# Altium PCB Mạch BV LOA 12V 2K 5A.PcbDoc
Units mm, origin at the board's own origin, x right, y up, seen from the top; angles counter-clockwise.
Board outline 69.27 x 57.96 mm, 2 copper layers (Top Layer, Bottom Layer); 0 components, 34 nets, 68 pads, 0 vias.
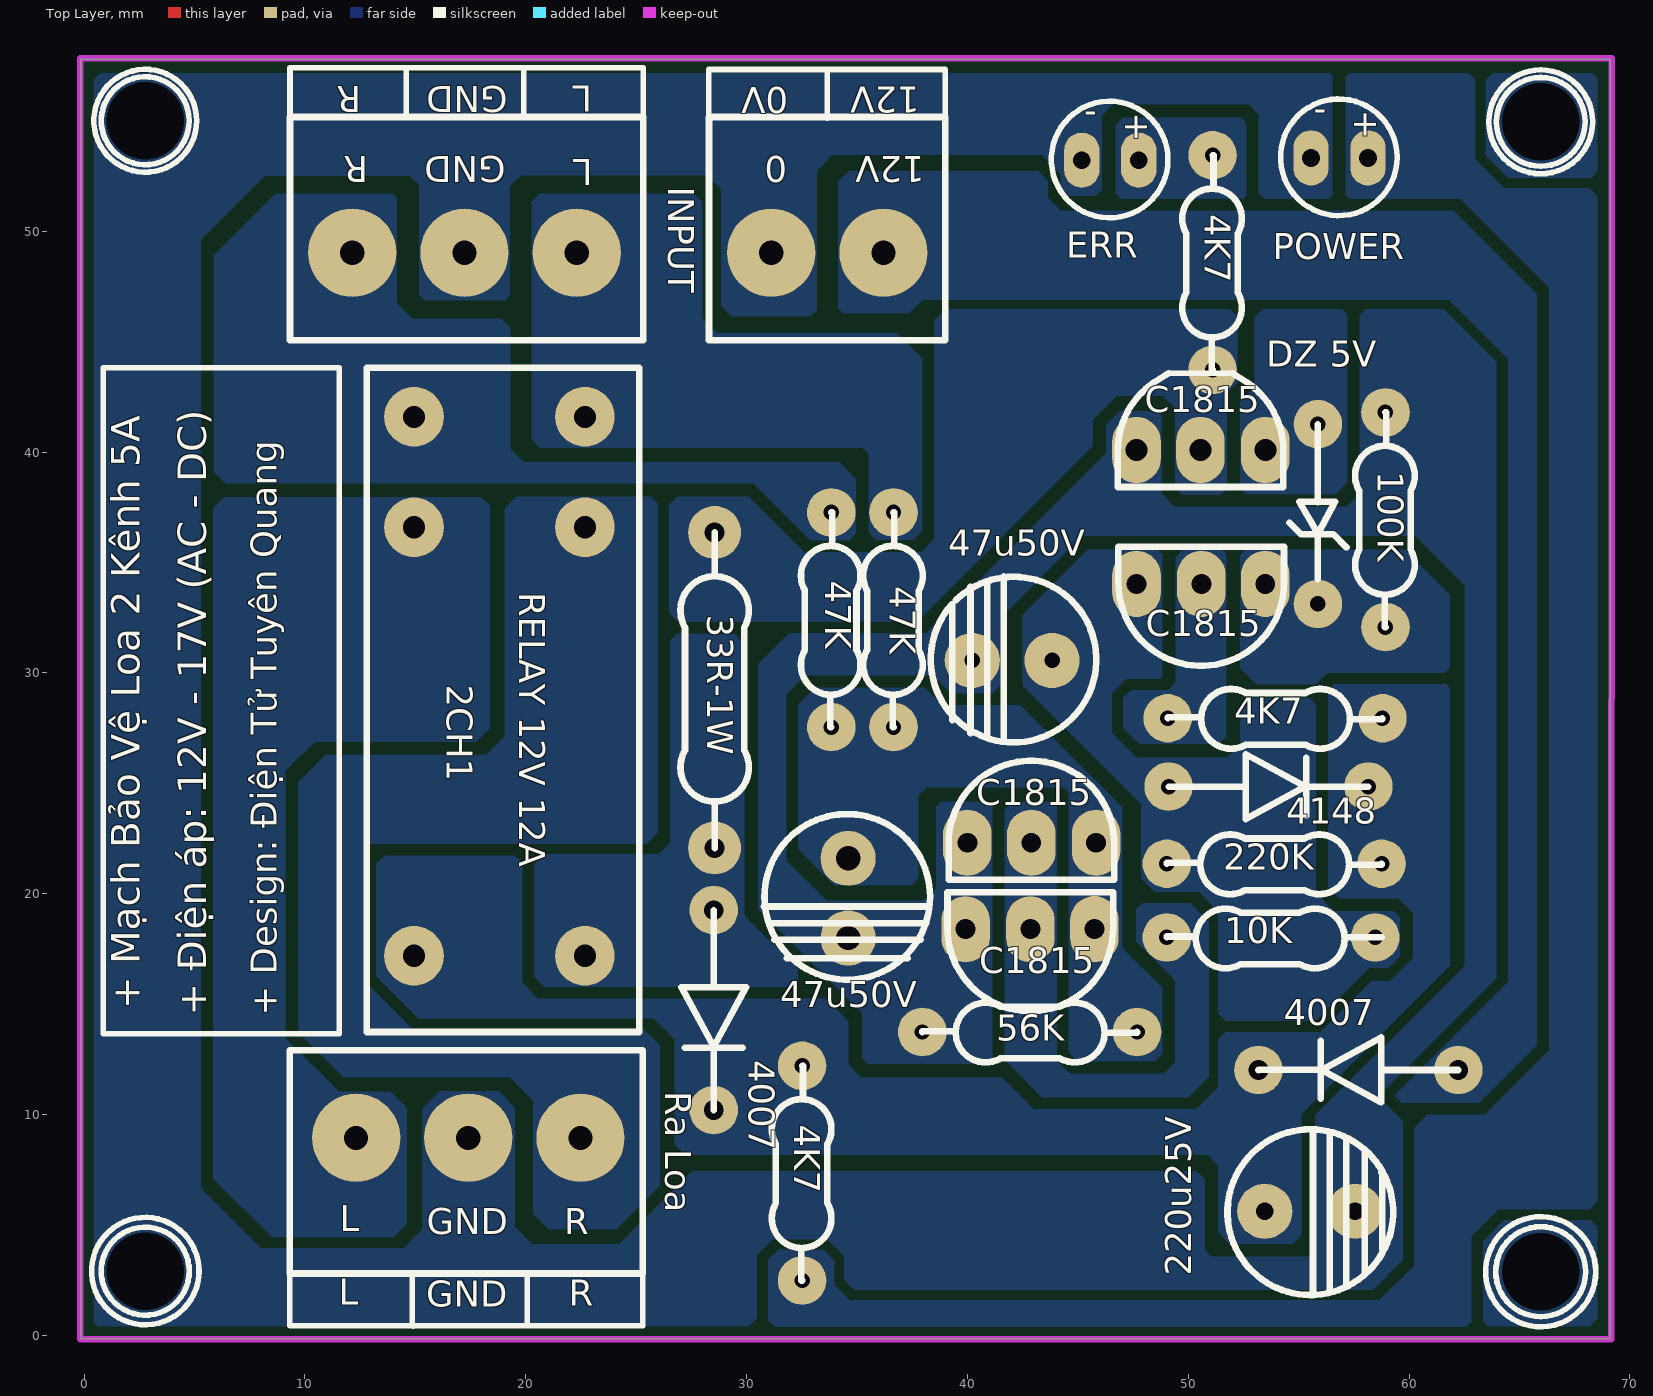
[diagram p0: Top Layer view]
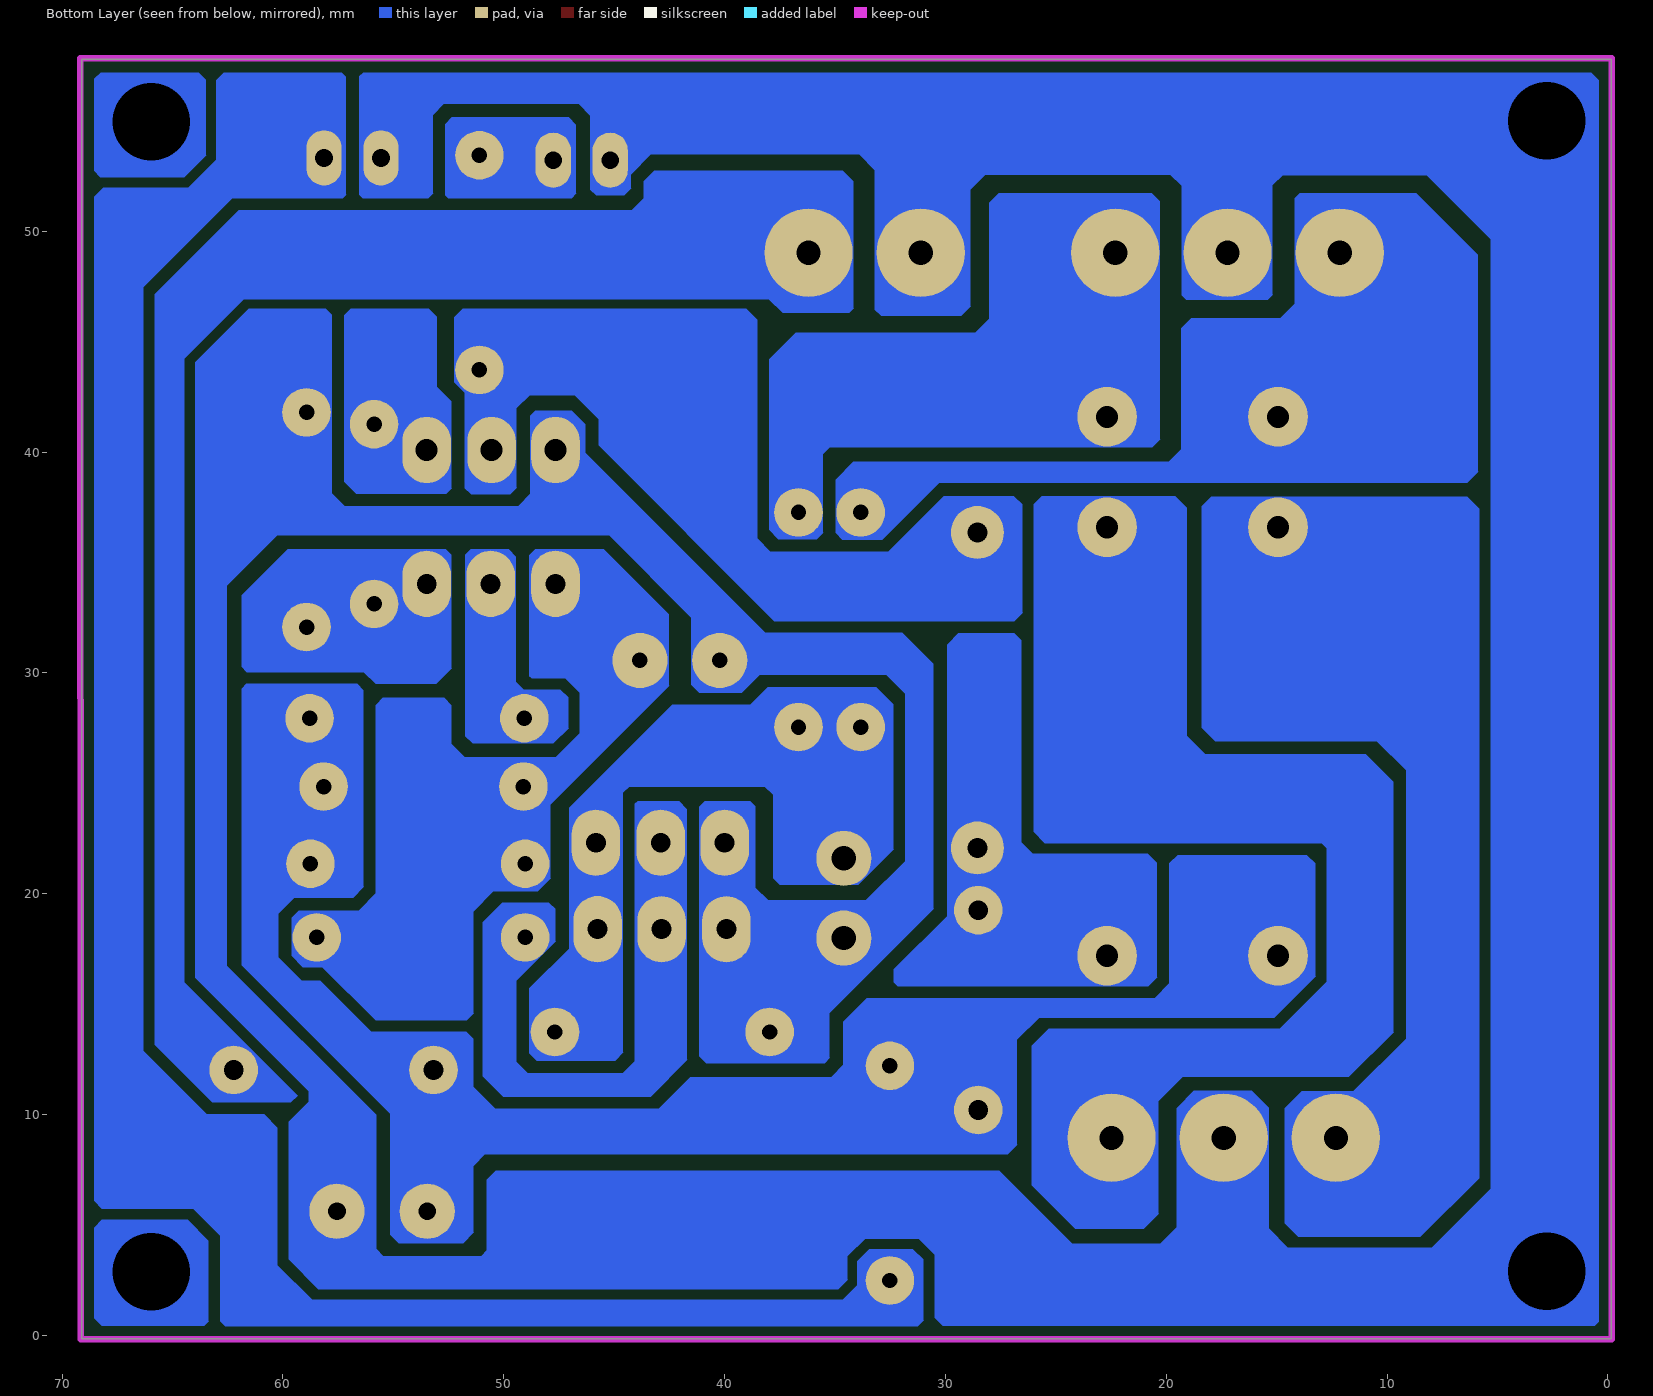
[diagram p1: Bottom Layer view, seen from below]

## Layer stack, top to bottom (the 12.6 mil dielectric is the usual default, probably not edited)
Top Solder: solder mask 0.0102, Solder Resist, Dk 3.5
Top Layer: signal copper 0.0356
Dielectric 1: dielectric 0.32, FR-4, Dk 4.8
Bottom Layer: signal copper 0.0356
Bottom Solder: solder mask 0.0102, Solder Resist, Dk 3.5

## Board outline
-0.152,57.799 69.113,57.799 69.113,-0.164 -0.152,-0.164

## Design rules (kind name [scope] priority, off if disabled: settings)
Clearance [All] p1: gap=0.254 ignorepadtopadclearanceinfootprint=FALSE except(0: Arc-Hole Track-Hole SMDPad-Hole THPad-Hole Via-Hole Fill-Hole Poly-Hole Region-Hole Text-Hole)
PolygonConnect CAM_PolygonConnect_$Net9 [InNet('$Net9')] p1: connectstyle=Direct reliefconductorwidth=0.254 reliefentries=4 polygonreliefangle="90 Angle" airgapwidth=0.254
PolygonConnect CAM_PolygonConnect_$Net18 [InNet('$Net18')] p2: connectstyle=Direct reliefconductorwidth=0.254 reliefentries=4 polygonreliefangle="90 Angle" airgapwidth=0.254
PolygonConnect CAM_PolygonConnect_$Net19 [InNet('$Net19')] p3: connectstyle=Direct reliefconductorwidth=0.254 reliefentries=4 polygonreliefangle="90 Angle" airgapwidth=0.254
PolygonConnect CAM_PolygonConnect_$Net29 [InNet('$Net29')] p4: connectstyle=Direct reliefconductorwidth=0.254 reliefentries=4 polygonreliefangle="90 Angle" airgapwidth=0.254
PolygonConnect CAM_PolygonConnect_$Net14 [InNet('$Net14')] p5: connectstyle=Direct reliefconductorwidth=0.254 reliefentries=4 polygonreliefangle="90 Angle" airgapwidth=0.254
PolygonConnect CAM_PolygonConnect_$Net17 [InNet('$Net17')] p6: connectstyle=Direct reliefconductorwidth=0.254 reliefentries=4 polygonreliefangle="90 Angle" airgapwidth=0.254
PolygonConnect CAM_PolygonConnect_$Net16 [InNet('$Net16')] p7: connectstyle=Direct reliefconductorwidth=0.254 reliefentries=4 polygonreliefangle="90 Angle" airgapwidth=0.254
PolygonConnect CAM_PolygonConnect_$Net8 [InNet('$Net8')] p8: connectstyle=Direct reliefconductorwidth=0.254 reliefentries=4 polygonreliefangle="90 Angle" airgapwidth=0.254
PolygonConnect CAM_PolygonConnect_$Net25 [InNet('$Net25')] p9: connectstyle=Direct reliefconductorwidth=0.254 reliefentries=4 polygonreliefangle="90 Angle" airgapwidth=0.254
PolygonConnect CAM_PolygonConnect_$Net7 [InNet('$Net7')] p10: connectstyle=Direct reliefconductorwidth=0.254 reliefentries=4 polygonreliefangle="90 Angle" airgapwidth=0.254
PolygonConnect CAM_PolygonConnect_$Net3 [InNet('$Net3')] p11: connectstyle=Direct reliefconductorwidth=0.254 reliefentries=4 polygonreliefangle="90 Angle" airgapwidth=0.254
PolygonConnect CAM_PolygonConnect_$Net4 [InNet('$Net4')] p12: connectstyle=Direct reliefconductorwidth=0.254 reliefentries=4 polygonreliefangle="90 Angle" airgapwidth=0.254
PolygonConnect CAM_PolygonConnect_$Net5 [InNet('$Net5')] p13: connectstyle=Direct reliefconductorwidth=0.254 reliefentries=4 polygonreliefangle="90 Angle" airgapwidth=0.254
PolygonConnect CAM_PolygonConnect_$Net6 [InNet('$Net6')] p14: connectstyle=Direct reliefconductorwidth=0.254 reliefentries=4 polygonreliefangle="90 Angle" airgapwidth=0.254
PolygonConnect CAM_PolygonConnect_$Net15 [InNet('$Net15')] p15: connectstyle=Direct reliefconductorwidth=0.254 reliefentries=4 polygonreliefangle="90 Angle" airgapwidth=0.254
PolygonConnect CAM_PolygonConnect_$Net2 [InNet('$Net2')] p16: connectstyle=Direct reliefconductorwidth=0.254 reliefentries=4 polygonreliefangle="90 Angle" airgapwidth=0.254
PolygonConnect CAM_PolygonConnect_$Net1 [InNet('$Net1')] p17: connectstyle=Direct reliefconductorwidth=0.254 reliefentries=4 polygonreliefangle="90 Angle" airgapwidth=0.254
PolygonConnect CAM_PolygonConnect_$Net26 [InNet('$Net26')] p18: connectstyle=Direct reliefconductorwidth=0.254 reliefentries=4 polygonreliefangle="90 Angle" airgapwidth=0.254
PolygonConnect CAM_PolygonConnect_$Net20 [InNet('$Net20')] p19: connectstyle=Direct reliefconductorwidth=0.254 reliefentries=4 polygonreliefangle="90 Angle" airgapwidth=0.254
PolygonConnect CAM_PolygonConnect_$Net21 [InNet('$Net21')] p20: connectstyle=Direct reliefconductorwidth=0.254 reliefentries=4 polygonreliefangle="90 Angle" airgapwidth=0.254
PolygonConnect CAM_PolygonConnect_$Net11 [InNet('$Net11')] p21: connectstyle=Direct reliefconductorwidth=0.254 reliefentries=4 polygonreliefangle="90 Angle" airgapwidth=0.254
PolygonConnect CAM_PolygonConnect_$Net10 [InNet('$Net10')] p22: connectstyle=Direct reliefconductorwidth=0.254 reliefentries=4 polygonreliefangle="90 Angle" airgapwidth=0.254
PolygonConnect CAM_PolygonConnect_$Net12 [InNet('$Net12')] p23: connectstyle=Direct reliefconductorwidth=0.254 reliefentries=4 polygonreliefangle="90 Angle" airgapwidth=0.254
PolygonConnect CAM_PolygonConnect_$Net13 [InNet('$Net13')] p24: connectstyle=Direct reliefconductorwidth=0.254 reliefentries=4 polygonreliefangle="90 Angle" airgapwidth=0.254
PolygonConnect CAM_PolygonConnect_$Net0 [InNet('$Net0')] p25: connectstyle=Direct reliefconductorwidth=0.254 reliefentries=4 polygonreliefangle="90 Angle" airgapwidth=0.254
PolygonConnect CAM_PolygonConnect_$Net31 [InNet('$Net31')] p26: connectstyle=Direct reliefconductorwidth=0.254 reliefentries=4 polygonreliefangle="90 Angle" airgapwidth=0.254
PolygonConnect CAM_PolygonConnect_$Net30 [InNet('$Net30')] p27: connectstyle=Direct reliefconductorwidth=0.254 reliefentries=4 polygonreliefangle="90 Angle" airgapwidth=0.254
PolygonConnect CAM_PolygonConnect_$Net23 [InNet('$Net23')] p28: connectstyle=Direct reliefconductorwidth=0.254 reliefentries=4 polygonreliefangle="90 Angle" airgapwidth=0.254
PolygonConnect CAM_PolygonConnect_$Net22 [InNet('$Net22')] p29: connectstyle=Direct reliefconductorwidth=0.254 reliefentries=4 polygonreliefangle="90 Angle" airgapwidth=0.254
PolygonConnect CAM_PolygonConnect_$Net27 [InNet('$Net27')] p30: connectstyle=Direct reliefconductorwidth=0.254 reliefentries=4 polygonreliefangle="90 Angle" airgapwidth=0.254
PolygonConnect CAM_PolygonConnect_$Net24 [InNet('$Net24')] p31: connectstyle=Direct reliefconductorwidth=0.254 reliefentries=4 polygonreliefangle="90 Angle" airgapwidth=0.254
PolygonConnect CAM_PolygonConnect_$Net28 [InNet('$Net28')] p32: connectstyle=Direct reliefconductorwidth=0.254 reliefentries=4 polygonreliefangle="90 Angle" airgapwidth=0.254
PolygonConnect CAM_PolygonConnect_$Net32 [InNet('$Net32')] p33: connectstyle=Direct reliefconductorwidth=0.254 reliefentries=4 polygonreliefangle="90 Angle" airgapwidth=0.254
PolygonConnect [All] p34: connectstyle=Relief reliefconductorwidth=0.254 reliefentries=4 polygonreliefangle="90 Angle" airgapwidth=0.254
RoutingVias [All] p1: holewidth=0.711 width=1.27 viastyle="Through Hole" minholewidth=0.711 minwidth=1.27 maxholewidth=0.711 maxwidth=1.27
SolderMaskExpansion [All] p1: expansion=0.102
Width [All] p1: maxlimit=0.254 minlimit=0.254 preferedwidth=0.254
30 further rules are at their usual default settings.

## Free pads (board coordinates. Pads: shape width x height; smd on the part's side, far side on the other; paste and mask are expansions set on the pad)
  round 0 hole 3.5: 1(2.769,2.909) 1(2.769,55.005) 1(65.964,2.882) 1(65.964,54.954)
  round 4 hole 1.1: 1(12.143,49.032) 1(12.317,8.942) 1(17.223,49.032) 1(17.397,8.942) 1(22.303,49.032) 1(22.477,8.942) 1(31.117,49.032) 1(36.197,49.032)
  round 2.7 hole 1: 1(14.94,36.597) 1(14.94,41.598) 1(14.94,17.19) 1(22.679,17.19) 1(22.679,36.597) 1(22.679,41.598)
  round 2.2 hole 0.9: 1(28.513,10.205) 1(28.513,19.254) 1(53.181,12.02) 1(62.23,12.02)
  round 2.4 hole 0.9: 1(28.552,22.072) 1(28.552,36.359)
  round 2.2 hole 0.7: 1(32.517,2.485) 1(32.517,12.208) 1(33.836,27.543) 1(33.836,37.267) 1(36.654,27.543) 1(36.654,37.267) 1(37.958,13.737) 1(47.682,13.737) 1(49.031,18.024) 1(49.031,21.357) 1(49.071,27.945) 1(49.111,24.85) 1(51.105,43.719) 1(51.105,53.442) 1(55.872,33.126) 1(55.872,41.262) 1(58.159,24.85) 1(58.471,18.024) 1(58.755,21.357) 1(58.794,27.945) 1(58.933,32.076) 1(58.933,41.799)
  round 2.5 hole 1.1: 1(34.599,17.99) 1(34.599,21.602)
  oval 2.2x3 hole 0.9: 1(39.917,18.395) 1(39.997,22.311) 1(42.854,18.395) 1(42.894,22.311) 1(45.751,18.395) 1(45.831,22.311) 1(47.656,34.032) 1(50.593,34.032) 1(53.49,34.032)
  round 2.5 hole 0.7: 1(40.221,30.565) 1(43.832,30.565)
  oval 1.6x2.5 hole 0.8: 1(45.18,53.217) 1(47.76,53.217) 1(55.561,53.32) 1(58.141,53.32)
  oval 2.2x3 hole 1: 1(47.656,40.095) 1(50.553,40.095) 1(53.49,40.095)
  round 2.5 hole 0.8: 1(53.469,5.619) 1(57.556,5.619)

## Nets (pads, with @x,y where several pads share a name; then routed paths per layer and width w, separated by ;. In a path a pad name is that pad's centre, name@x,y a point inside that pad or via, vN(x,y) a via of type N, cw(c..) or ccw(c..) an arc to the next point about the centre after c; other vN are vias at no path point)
$Net0: pad.1@2.769,2.909 pad.1@2.769,55.005 pad.1@17.223,49.032 pad.1@17.397,8.942 pad.1@31.117,49.032 pad.1@34.599,17.99 pad.1@37.958,13.737 pad.1@39.917,18.395 pad.1@39.997,22.311 pad.1@40.221,30.565 pad.1@45.18,53.217 pad.1@47.656,40.095 pad.1@55.561,53.32 pad.1@57.556,5.619 pad.1@58.933,41.799 | length 877.8
  Bottom Layer w0.01: 0.432,0.623 0.432,56.834 0.762,57.164 4.674,57.164 56.363,57.164 56.515,57.011 56.515,51.652 56.363,51.5 53.442,51.5 53.213,51.728 53.213,55.284 52.73,55.767 46.584,55.767 46.05,55.233 46.05,51.881 45.796,51.627 44.577,51.627 44.247,51.957 44.247,52.592 43.358,53.481 33.884,53.481 33.172,52.77 33.172,46.445 32.893,46.166 29.312,46.166 28.88,46.597 28.88,51.906 28.219,52.566 19.787,52.566 19.279,52.058 19.279,47.105 19.075,46.902 15.418,46.902 15.189,47.131 15.189,52.109 14.757,52.541 8.179,52.541 5.283,49.645 5.283,6.643 7.97,3.956 14.491,3.956 15.367,4.832 15.367,10.287 16.129,11.049 18.745,11.049 19.507,10.287 19.507,4.891 20.269,4.129 24.257,4.129 27.559,7.431 50.368,7.431 50.749,7.05 50.749,3.849 51.029,3.57 55.448,3.57 55.778,3.9 55.778,9.957 62.535,16.713 62.535,33.974 60.274,36.234 45.212,36.234 41.478,32.5 41.478,29.452 41.123,29.097 39.243,29.097 38.43,29.91 32.664,29.91 31.801,29.046 31.801,21.477 33.604,19.673 38.024,19.673 38.608,20.258 38.608,23.941 38.837,24.169 40.894,24.169 41.123,23.941 41.123,12.638 40.818,12.333 35.484,12.333 35.255,12.561 35.255,14.619 30.556,19.318 30.556,30.392 31.953,31.789 38.151,31.789 46.304,39.943 46.304,41.238 46.914,41.848 48.565,41.848 48.768,41.644 48.768,38.114 49.352,37.53 57.201,37.53 57.785,38.114 57.785,46.191 58.064,46.47 61.544,46.47 63.957,44.057 63.957,16.205 58.801,11.049 58.801,10.58 59.715,9.666 59.715,3.443 58.369,2.097 34.874,2.097 34.442,2.528 34.442,3.595 33.655,4.383 31.191,4.383 30.455,3.646 30.455,0.801 30.099,0.446 0.61,0.446 0.432,0.623
  Bottom Layer w0.254: pad.1@17.223,47.209 pad.1@17.223,49.032 ; 17.223,56.351 17.223,52.789 17.755,53.32 30.556,53.32 31.117,52.759 pad.1@31.117,49.032 ; 17.397,1.047 pad.1@17.397,8.942 ; pad.1@37.958,13.737 37.958,16.436 pad.1@39.917,18.395 ; pad.1@39.997,22.311 39.997,18.474 pad.1@39.917,18.395 ; pad.1@45.18,53.217 45.18,55.829 45.796,56.444 ; pad.1@55.561,53.32 54.221,53.32 53.772,53.769 53.772,56.444 45.796,56.444 ; pad.1@57.556,5.619 57.556,5.263 55.601,3.308 35.128,3.308 33.833,4.603 30.912,4.603 27.305,0.996 5.545,0.996 4.877,1.665 4.877,55.767 5.555,56.444 45.796,56.444 ; pad.1@58.191,41.799 pad.1@58.933,41.058 ; 61.671,41.086 60.958,41.799 58.933,41.799 pad.1@58.933,41.058 ; pad.1@39.917,18.395 35.003,18.395 34.599,17.99 31.166,21.423 31.166,29.783 32.352,30.968 39.817,30.968 40.221,30.565 40.221,32.66 47.656,40.095 47.656,38.328 49.098,36.886 57.76,36.886 58.933,38.06 pad.1@58.933,41.058
  Bottom Layer w2: pad.1@17.223,49.032 17.223,52.789
$Net1: pad.1@12.143,49.032 pad.1@14.94,41.598 pad.1@33.836,37.267 | length 113.5
  Bottom Layer w0.01: 5.893,39.116 6.387,38.622 30.302,38.622 32.893,36.031 34.646,36.031 34.95,36.336 34.95,38.749 34.163,39.536 19.888,39.536 19.304,40.12 19.304,45.607 18.872,46.039 14.834,46.039 14.148,46.724 14.148,51.5 13.945,51.703 8.687,51.703 5.893,48.909 5.893,39.116
  Bottom Layer w0.254: pad.1@12.143,49.032 12.143,44.394 14.94,41.598 17.213,39.325 31.778,39.325 pad.1@33.836,37.267
$Net2: pad.1@22.303,49.032 pad.1@22.679,41.598 pad.1@36.654,37.267 | length 91.3
  Bottom Layer w0.01: pad.1@20.345,49.032 pad.1@22.303,49.032 ; 20.295,40.578 20.65,40.222 35.255,40.222 35.547,39.93 35.547,36.348 35.839,36.056 37.541,36.056 37.958,36.474 37.958,44.199 36.779,45.378 28.651,45.378 27.991,46.039 27.991,51.296 27.584,51.703 20.65,51.703 20.295,51.347 20.295,40.578
  Bottom Layer w0.254: pad.1@22.303,49.032 22.303,41.973 22.679,41.598 35.116,41.598 36.654,40.059 pad.1@36.654,37.267
$Net3: pad.1@12.317,8.942 pad.1@14.94,36.597 | length 133.6
  Bottom Layer w0.01: 5.842,7.126 5.842,37.44 6.364,37.961 17.958,37.961 18.364,37.555 18.364,27.522 17.755,26.912 10.439,26.912 9.119,25.592 9.119,13.425 11.52,11.024 13.868,11.024 14.605,10.287 14.605,5.068 13.995,4.459 8.509,4.459 5.842,7.126
  Bottom Layer w0.254: pad.1@12.317,8.942 10.597,8.942 8.811,10.728 8.811,36.155 9.253,36.597 pad.1@14.94,36.597
$Net4: pad.1@22.477,8.942 pad.1@22.679,36.597 | length 165.5
  Bottom Layer w0.01: 9.728,13.73 11.749,11.709 19.279,11.709 20.371,10.617 20.371,5.5 21.049,4.822 24.087,4.822 26.06,6.796 26.06,13.12 25.324,13.857 14.859,13.857 12.7,16.016 12.7,22.061 12.929,22.29 25.476,22.29 25.984,22.798 25.984,37.631 25.629,37.987 19.596,37.987 19.075,37.466 19.075,27.141 18.237,26.303 10.973,26.303 9.728,25.058 9.728,13.73
  Bottom Layer w0.254: pad.1@22.477,8.942 22.477,11.362 20.625,13.214 12.929,13.214 11.379,14.763 11.379,22.798 12.184,23.602 21.895,23.602 22.679,24.386 pad.1@22.679,36.597
$Net5: pad.1@14.94,17.19 pad.1@28.513,10.205 pad.1@32.517,12.208 pad.1@53.181,12.02 pad.1@53.469,5.619 pad.1@58.159,24.85 pad.1@58.755,21.357 pad.1@58.794,27.945 | length 242
  Bottom Layer w0.01: 13.259,16.27 13.259,21.35 13.64,21.731 19.482,21.731 19.837,21.375 19.837,15.94 20.523,15.254 33.553,15.254 34.599,14.208 34.599,12.253 35.179,11.672 41.554,11.672 42.977,10.25 50.394,10.25 51.384,11.241 51.384,13.411 51.703,13.73 56.007,13.73 58.318,16.041 59.157,16.041 60.223,17.108 60.223,19.115 59.512,19.826 56.845,19.826 56.363,20.308 56.363,29.198 56.642,29.478 61.657,29.478 61.849,29.286 61.849,16.764 55.118,10.033 55.118,4.56 54.737,4.179 51.867,4.179 51.384,4.662 51.384,7.685 50.876,8.193 27.203,8.193 26.772,8.624 26.772,13.4 25.781,14.39 15.138,14.39 13.259,16.27
  Bottom Layer w0.254: pad.1@13.735,17.19 14.94,17.19 16.123,17.19 18.575,14.738 26.67,14.738 28.513,12.895 28.513,10.205 31.555,10.205 32.644,11.294 36.159,11.294 38.075,9.378 51.132,9.378 53.469,7.041 ; pad.1@53.469,5.619 53.469,7.041 ; pad.1@58.794,27.945 58.159,27.31 58.159,24.85 58.755,24.254 58.755,21.357 60.655,19.457 60.655,16.846 55.982,12.172 51.987,12.172 53.469,10.691 53.469,7.041
$Net6: pad.1@22.679,17.19 pad.1@28.513,19.254 pad.1@28.552,22.072 | length 62.4
  Bottom Layer w0.01: 20.422,16.219 20.422,21.375 20.828,21.782 26.035,21.782 26.568,22.315 26.568,31.459 26.873,31.764 29.413,31.764 29.896,31.281 29.896,18.988 32.309,16.575 32.309,15.99 32.131,15.813 20.828,15.813 20.422,16.219
  Bottom Layer w0.254: pad.1@22.679,17.19 26.449,17.19 28.513,19.254 28.513,22.032 pad.1@28.552,22.072
$Net7: pad.1@28.552,36.359 pad.1@50.553,40.095 pad.1@51.105,43.719 | length 117.9
  Bottom Layer w0.01: pad.1@49.504,40.095 pad.1@50.553,40.095 ; 26.518,32.729 26.518,37.606 26.899,37.987 30.074,37.987 32.588,35.472 37.922,35.472 38.532,36.082 38.532,45.975 39.027,46.47 51.867,46.47 52.222,46.115 52.222,43.168 51.74,42.686 51.74,38.368 51.46,38.088 49.733,38.088 49.428,38.393 49.428,42 48.844,42.584 46.761,42.584 45.669,41.492 45.669,40.298 37.719,32.348 26.899,32.348 26.518,32.729
  Bottom Layer w0.254: pad.1@28.552,36.359 31.937,32.975 36.464,32.975 47.209,43.719 51.105,43.719 51.105,40.646 pad.1@50.553,40.095
$Net8: 
$Net9: pad.1@53.49,40.095 pad.1@55.872,41.262 | length 29
  Bottom Layer w0.01: pad.1@52.445,40.095 pad.1@53.49,40.095 ; 52.375,38.368 52.375,42.279 53.035,42.94 53.035,46.102 53.404,46.47 54.153,46.47 56.921,46.47 57.201,46.191 57.201,38.647 56.667,38.114 52.629,38.114 52.375,38.368
  Bottom Layer w0.254: pad.1@53.49,40.095 54.705,40.095 pad.1@55.872,41.262
$Net10: pad.1@53.49,34.032 pad.1@55.872,33.126 pad.1@58.933,32.076 | length 35.1
  Bottom Layer w0.01: 52.375,30.214 52.375,35.32 52.629,35.574 59.792,35.574 61.849,33.516 61.849,30.277 61.609,30.037 56.312,30.037 55.778,29.503 53.086,29.503 52.375,30.214
  Bottom Layer w0.254: pad.1@53.49,34.032 54.966,34.032 55.872,33.126 57.882,33.126 pad.1@58.933,32.076
$Net11: pad.1@49.071,27.945 pad.1@50.593,34.032 | length 32.3
  Bottom Layer w0.01: 47.092,27.497 47.092,28.868 47.447,29.224 49.098,29.224 49.454,29.579 49.454,35.244 49.784,35.574 51.486,35.574 51.714,35.345 51.714,27.139 51.386,26.811 47.777,26.811 47.092,27.497
  Bottom Layer w0.254: pad.1@49.071,27.945 50.749,29.624 50.749,33.876 pad.1@50.593,34.032
$Net12: pad.1@43.832,30.565 pad.1@47.656,34.032 pad.1@49.031,21.357 pad.1@49.111,24.85 pad.1@58.471,18.024 | length 104.9
  Bottom Layer w0.01: 42.52,29.427 42.52,32.627 45.466,35.574 48.565,35.574 48.819,35.32 48.819,29.859 48.717,29.757 47.193,29.757 46.533,29.097 46.533,27.268 47.65,26.15 51.765,26.15 52.375,26.76 52.375,28.513 52.705,28.843 55.474,28.843 55.778,28.538 55.778,20.016 56.578,19.216 59.284,19.216 59.588,18.911 59.588,17.184 59.08,16.676 58.191,16.676 55.778,14.263 51.701,14.263 51.384,14.58 51.384,19.216 50.495,20.105 48.489,20.105 47.904,20.689 47.904,24.042 42.52,29.427
  Bottom Layer w0.254: pad.1@47.656,34.032 44.189,30.565 43.832,30.565 43.832,28.487 47.47,24.85 49.111,24.85 49.031,24.77 49.031,21.357 51.377,21.357 54.71,18.024 pad.1@58.471,18.024
$Net13: 
$Net14: 
$Net15: pad.1@33.836,27.543 pad.1@34.599,21.602 pad.1@36.654,27.543 pad.1@45.751,18.395 pad.1@45.831,22.311 pad.1@47.682,13.737 | length 100.1
  Bottom Layer w0.01: 32.36,22.018 32.36,28.563 33.122,29.325 38.043,29.325 38.83,28.538 42.367,28.538 47.015,23.89 47.015,17.514 48.819,15.711 48.819,12.765 48.489,12.434 44.983,12.434 44.602,12.815 44.602,24.601 44.348,24.855 38.151,24.855 37.77,24.474 37.77,20.689 37.478,20.397 33.98,20.397 32.36,22.018
  Bottom Layer w0.254: pad.1@34.599,21.602 34.599,26.781 33.836,27.543 36.654,27.543 42.719,27.543 45.831,24.431 45.831,22.311 45.831,18.474 45.751,18.395 47.682,16.464 pad.1@47.682,13.737
$Net16: pad.1@42.854,18.395 pad.1@42.894,22.311 pad.1@49.031,18.024 | length 84.2
  Bottom Layer w0.01: 41.707,12.477 43.375,10.809 50.013,10.809 50.927,11.723 50.927,18.708 50.063,19.572 47.955,19.572 47.676,19.292 47.676,17.845 49.428,16.092 49.428,12.358 48.92,11.85 44.602,11.85 44.044,12.409 44.044,24.068 43.942,24.169 42.062,24.169 41.707,23.814 41.707,12.477
  Bottom Layer w0.254: pad.1@42.894,22.311 42.854,22.271 42.854,18.395 42.854,12.193 43.84,11.207 49.352,11.207 49.606,11.461 49.606,17.449 pad.1@49.031,18.024
$Net17: 
$Net18: pad.1@36.197,49.032 pad.1@62.23,12.02 | length 177.1
  Bottom Layer w0.01: 34.163,46.521 34.379,46.305 37.351,46.305 37.973,46.928 61.798,46.928 64.491,44.235 64.491,15.99 59.36,10.86 59.665,10.555 63.17,10.555 65.786,13.171 65.786,47.142 62.001,50.927 44.196,50.927 43.637,51.486 43.637,52.262 43.18,52.719 34.646,52.719 34.163,52.236 34.163,46.521
  Bottom Layer w0.254: pad.1@36.197,49.032 61.624,49.032 63.373,47.283
$Net19: 
$Net20: pad.1@32.517,2.485 pad.1@58.141,53.32 | length 244.1
  Bottom Layer w0.01: 62.586,0.406 62.599,0.42 ; 62.599,0.42 62.814,0.635 62.814,4.521 64.033,5.74 68.174,5.74 68.529,6.096 68.529,51.562 68.148,51.943 64.287,51.943 62.992,53.238 62.992,56.845 62.673,57.164 57.342,57.164 57.15,56.972 57.15,51.664 57.314,51.5 62.318,51.5 66.345,47.473 66.345,12.892 63.449,9.996 60.858,9.996 60.249,9.386 60.249,3.163 58.674,1.589 34.646,1.589 33.96,2.274 33.96,3.367 33.452,3.875 31.471,3.875 31.013,3.417 31.013,0.674 31.267,0.42 62.599,0.42
  Bottom Layer w0.254: pad.1@32.644,1.57 33.345,0.869 58.654,0.869 64.44,6.655 ; pad.1@58.141,53.32 62.695,53.32 64.44,51.576
$Net21: pad.1@47.76,53.217 pad.1@51.105,53.442 | length 21.9
  Bottom Layer w0.01: 46.736,51.715 46.952,51.5 52.502,51.5 52.629,51.627 52.629,54.852 52.349,55.132 47.066,55.132 46.736,54.802 46.736,51.715
  Bottom Layer w0.254: pad.1@47.76,53.217 47.986,53.442 pad.1@51.105,53.442
$Net22: pad.1@65.964,54.954 | length 18.4
  Bottom Layer w0.01: 63.5,53.442 63.5,56.845 63.819,57.164 68.261,57.164 68.529,56.896 68.529,52.73 68.25,52.451 64.491,52.451 63.5,53.442
$Net23: pad.1@65.964,2.882 | length 18.8
  Bottom Layer w0.01: 63.373,0.635 63.373,4.268 64.312,5.207 68.199,5.207 68.529,4.877 68.529,0.776 68.185,0.432 63.576,0.432 63.373,0.635
$Net24: 
$Net25: 
$Net26: 
$Net27: 
$Net28: 
$Net29: 
$Net30: 
$Net31: 
$Net32: 
$Net33: 

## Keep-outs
Keep-Out Layer:
  lines w0.3: -0.178,-0.164 -0.178,57.837 69.182,57.822 69.158,-0.179 -0.178,-0.164

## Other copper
Bottom Layer:
  region net $Net23: 63.373,4.268 64.312,5.207 68.199,5.207 68.529,4.877 68.529,0.776 68.185,0.432 63.576,0.432 63.373,0.635
  region net $Net22: 63.5,56.845 63.819,57.164 68.261,57.164 68.529,56.896 68.529,52.73 68.25,52.451 64.491,52.451 63.5,53.442
  region net $Net20: 57.15,56.972 57.342,57.164 62.673,57.164 62.992,56.845 62.992,53.238 64.287,51.943 68.148,51.943 68.529,51.562 68.529,6.096 68.174,5.74 64.033,5.74 62.814,4.521 62.814,0.635 62.599,0.42 31.267,0.42 31.013,0.674 31.013,3.417 31.471,3.875 33.452,3.875 33.96,3.367 33.96,2.274 34.646,1.589 58.674,1.589 60.249,3.163 60.249,9.386 60.858,9.996 63.449,9.996 66.345,12.892 66.345,47.473 62.318,51.5 57.314,51.5 57.15,51.664
  region net $Net16: 41.707,23.814 42.062,24.169 43.942,24.169 44.044,24.068 44.044,12.409 44.602,11.85 48.92,11.85 49.428,12.358 49.428,16.092 47.676,17.845 47.676,19.292 47.955,19.572 50.063,19.572 50.927,18.708 50.927,11.723 50.013,10.809 43.375,10.809 41.707,12.477
  region net $Net15: 32.36,28.563 33.122,29.325 38.043,29.325 38.83,28.538 42.367,28.538 47.015,23.89 47.015,17.514 48.819,15.711 48.819,12.765 48.489,12.434 44.983,12.434 44.602,12.815 44.602,24.601 44.348,24.855 38.151,24.855 37.77,24.474 37.77,20.689 37.478,20.397 33.98,20.397 32.36,22.018
  region net $Net10: 52.375,35.32 52.629,35.574 59.792,35.574 61.849,33.516 61.849,30.277 61.609,30.037 56.312,30.037 55.778,29.503 53.086,29.503 52.375,30.214
  region net $Net11: 49.454,35.244 49.784,35.574 51.486,35.574 51.714,35.345 51.714,27.139 51.386,26.811 47.777,26.811 47.092,27.497 47.092,28.868 47.447,29.224 49.098,29.224 49.454,29.579
  region net $Net12: 45.466,35.574 48.565,35.574 48.819,35.32 48.819,29.859 48.717,29.757 47.193,29.757 46.533,29.097 46.533,27.268 47.65,26.15 51.765,26.15 52.375,26.76 52.375,28.513 52.705,28.843 55.474,28.843 55.778,28.538 55.778,20.016 56.578,19.216 59.284,19.216 59.588,18.911 59.588,17.184 59.08,16.676 58.191,16.676 55.778,14.263 51.701,14.263 51.384,14.58 51.384,19.216 50.495,20.105 48.489,20.105 47.904,20.689 47.904,24.042 42.52,29.427 42.52,32.627
  region net $Net6: 26.568,31.459 26.873,31.764 29.413,31.764 29.896,31.281 29.896,18.988 32.309,16.575 32.309,15.99 32.131,15.813 20.828,15.813 20.422,16.219 20.422,21.375 20.828,21.782 26.035,21.782 26.568,22.315
  region net $Net5: 13.259,21.35 13.64,21.731 19.482,21.731 19.837,21.375 19.837,15.94 20.523,15.254 33.553,15.254 34.599,14.208 34.599,12.253 35.179,11.672 41.554,11.672 42.977,10.25 50.394,10.25 51.384,11.241 51.384,13.411 51.703,13.73 56.007,13.73 58.318,16.041 59.157,16.041 60.223,17.108 60.223,19.115 59.512,19.826 56.845,19.826 56.363,20.308 56.363,29.198 56.642,29.478 61.657,29.478 61.849,29.286 61.849,16.764 55.118,10.033 55.118,4.56 54.737,4.179 51.867,4.179 51.384,4.662 51.384,7.685 50.876,8.193 27.203,8.193 26.772,8.624 26.772,13.4 25.781,14.39 15.138,14.39 13.259,16.27
  region net $Net9: 53.035,46.102 53.404,46.47 56.921,46.47 57.201,46.191 57.201,38.647 56.667,38.114 52.629,38.114 52.375,38.368 52.375,42.279 53.035,42.94
  region net $Net7: 38.532,45.975 39.027,46.47 51.867,46.47 52.222,46.115 52.222,43.168 51.74,42.686 51.74,38.368 51.46,38.088 49.733,38.088 49.428,38.393 49.428,42 48.844,42.584 46.761,42.584 45.669,41.492 45.669,40.298 37.719,32.348 26.899,32.348 26.518,32.729 26.518,37.606 26.899,37.987 30.074,37.987 32.588,35.472 37.922,35.472 38.532,36.082
  region net $Net4: 19.075,37.466 19.596,37.987 25.629,37.987 25.984,37.631 25.984,22.798 25.476,22.29 12.929,22.29 12.7,22.061 12.7,16.016 14.859,13.857 25.324,13.857 26.06,13.12 26.06,6.796 24.087,4.822 21.049,4.822 20.371,5.5 20.371,10.617 19.279,11.709 11.749,11.709 9.728,13.73 9.728,25.058 10.973,26.303 18.237,26.303 19.075,27.141
  region net $Net3: 5.842,37.44 6.364,37.961 17.958,37.961 18.364,37.555 18.364,27.522 17.755,26.912 10.439,26.912 9.119,25.592 9.119,13.425 11.52,11.024 13.868,11.024 14.605,10.287 14.605,5.068 13.995,4.459 8.509,4.459 5.842,7.126
  region net $Net18: 34.163,52.236 34.646,52.719 43.18,52.719 43.637,52.262 43.637,51.511 44.221,50.927 62.001,50.927 65.786,47.142 65.786,13.171 63.17,10.555 59.665,10.555 59.36,10.86 64.491,15.99 64.491,44.235 61.798,46.928 37.973,46.928 37.351,46.305 34.379,46.305 34.163,46.521
  region net $Net21: 46.736,54.802 47.066,55.132 52.349,55.132 52.629,54.852 52.629,51.627 52.502,51.5 46.952,51.5 46.736,51.715
  region net $Net2: 20.295,51.347 20.65,51.703 27.584,51.703 27.915,51.373 27.991,51.296 27.991,46.039 28.651,45.378 36.779,45.378 37.958,44.199 37.958,36.474 37.541,36.056 35.839,36.056 35.547,36.348 35.547,39.93 35.255,40.222 20.65,40.222 20.295,40.578
  region net $Net1: 5.893,48.909 8.687,51.703 13.945,51.703 14.148,51.5 14.148,46.724 14.834,46.039 18.872,46.039 19.304,45.607 19.304,40.12 19.888,39.536 34.163,39.536 34.95,38.749 34.95,36.336 34.646,36.031 32.893,36.031 30.302,38.622 6.387,38.622 5.893,39.116
  region net $Net0: 14.757,52.541 15.189,52.109 15.189,47.131 15.418,46.902 19.075,46.902 19.279,47.105 19.279,52.058 19.787,52.566 28.219,52.566 28.88,51.906 28.88,46.597 29.312,46.166 32.893,46.166 33.172,46.445 33.172,52.77 33.884,53.481 43.358,53.481 44.247,52.592 44.247,51.957 44.577,51.627 45.796,51.627 46.076,51.906 46.076,55.259 46.584,55.767 52.73,55.767 53.213,55.284 53.213,51.728 53.442,51.5 56.363,51.5 56.515,51.652 56.515,57.011 56.363,57.164 0.762,57.164 0.432,56.834 0.432,0.623 0.61,0.446 30.099,0.446 30.455,0.801 30.455,3.646 31.191,4.383 33.655,4.383 34.442,3.595 34.442,2.528 34.874,2.097 58.369,2.097 59.715,3.443 59.715,9.666 58.801,10.58 58.801,11.049 63.957,16.205 63.957,44.057 61.544,46.47 58.064,46.47 57.785,46.191 57.785,38.114 57.201,37.53 49.352,37.53 48.768,38.114 48.768,41.644 48.565,41.848 46.914,41.848 46.304,41.238 46.304,39.943 38.151,31.789 31.953,31.789 30.556,30.392 30.556,19.318 35.255,14.619 35.255,12.561 35.484,12.333 40.97,12.333 40.818,12.333 41.123,12.638 41.123,23.941 40.894,24.169 38.837,24.169 38.608,23.941 38.608,20.258 38.024,19.673 33.604,19.673 31.801,21.477 31.801,29.046 32.664,29.91 38.43,29.91 39.243,29.097 41.123,29.097 41.478,29.452 41.478,32.5 45.212,36.234 60.274,36.234 62.535,33.974 62.535,16.713 55.778,9.957 55.778,3.9 55.448,3.57 51.029,3.57 50.749,3.849 50.749,7.05 50.368,7.431 27.559,7.431 24.257,4.129 20.269,4.129 19.507,4.891 19.507,10.287 18.745,11.049 16.115,11.049 15.367,10.301 15.367,4.822 14.501,3.956 7.97,3.956 5.283,6.643 5.283,49.645 8.179,52.541

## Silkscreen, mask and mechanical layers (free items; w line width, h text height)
Top Overlay:
  drawing of 1812 lines, arcs and shapes, not listed
  text "L" at 23.009,56.978 h2 r180
  text "R" at 12.548,56.952 h2 r180
  text "GND" at 19.177,56.947 h2 r180
  text "12V" at 37.846,56.921 h2 r180
  text "0V" at 31.877,56.896 h2 r180
  text "+" at 57.141,55.5 h2 r270
  text "+" at 46.76,55.397 h2 r270
  text "-" at 55.677,54.6 h2
  text "-" at 45.297,54.497 h2
  text "R" at 12.878,53.777 h2 r180
  text "GND" at 19.101,53.777 h2 r180
  text "0" at 31.852,53.777 h2 r180
  text "12V" at 38.075,53.777 h2 r180
  text "L" at 23.038,53.65 h2 r180
  text "INPUT" at 26.06,52.008 h2 r270
  text "4K7" at 50.363,50.765 h2 r270
  text "ERR" at 44.475,48.426 h2
  text "POWER" at 53.823,48.35 h2
  text "DZ 5V" at 53.543,43.49 h2
  text "C1815" at 48.031,41.412 h2
  text "100K" at 58.191,39.122 h2 r270
  text "47u50V" at 39.141,34.931 h2
  text "47K" at 33.172,34.169 h2 r270
  text "47K" at 36.093,33.915 h2 r270
  text "RELAY 12V 12A" at 19.329,33.661 h2 r270
  text "33R-1W" at 27.838,32.645 h2 r270
  text "C1815" at 48.079,31.283 h2
  text "2CH1" at 16.027,29.47 h2 r270
  text "4K7" at 52.095,27.311 h2
  text "C1815" at 40.411,23.628 h2
  text "4148" at 54.432,22.789 h2
  text "220K" at 51.587,20.707 h2
  text "10K" at 51.638,17.379 h2
  text "C1815" at 40.538,16.008 h2
  text "+ Mạch Bảo Vệ Loa 2 Kênh 5A" at 2.946,14.757 h2.2 r90
  text "+ Điện áp: 12V - 17V (AC - DC)" at 5.969,14.478 h2.2 r90
  text "+ Design: Điện Tử Tuyên Quang" at 9.119,14.478 h2 r90
  text "47u50V" at 31.521,14.484 h2
  text "4007" at 54.331,13.665 h2
  text "56K" at 41.3,12.96 h2
  text "4007" at 29.718,12.46 h2 r270
  text "Ra Loa" at 25.933,11.055 h2 r270
  text "4K7" at 31.775,9.531 h2 r270
  text "L" at 11.582,4.324 h2
  text "GND" at 15.519,4.197 h2
  text "R" at 21.742,4.197 h2
  text "220u25V" at 50.521,2.692 h2 r90
  text "L" at 11.532,0.996 h2
  text "R" at 21.946,0.945 h2
  text "GND" at 15.494,0.92 h2
Bottom Solder:
  lines w1: 17.223,49.032 17.223,54.354 16.51,55.067 7.493,55.067 3.505,51.079 3.505,6.426 7.823,2.108 15.723,2.108 17.397,3.782 17.397,8.942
